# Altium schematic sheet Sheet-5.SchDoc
size 431 x 279 mm; Date: Not shown in title block; ApprovedBy: Not shown in title block; CheckedBy: Not shown in title block; Author: Not shown in title block; CompanyName: Not shown in title block; Engineer: Not shown in title block; Organization: Not shown in title block; Address1: Not shown in title block; Address2: Not shown in title block; Address3: Not shown in title block; Address4: Not shown in title block; DocumentNumber: 3; Revision: Use project parameter SCH_Rev; SheetNumber: 3; SheetTotal: 4; PageSetup: Record=PageOptions|CenterHorizontal=True|CenterVertical=True|PrintScale=1.00|XCorrection=1.00|YCorrection=1.00|PrintKind=0|BorderSize=5000000|LeftOffset=0|BottomOffset=0|Orientation=2|PaperLength=1000|PaperWidth=1000|Scale=100|PaperSource=15|PrintQuality=600|MediaType=1|DitherType=10|PaperKind=Letter|PrintScaleMode=1
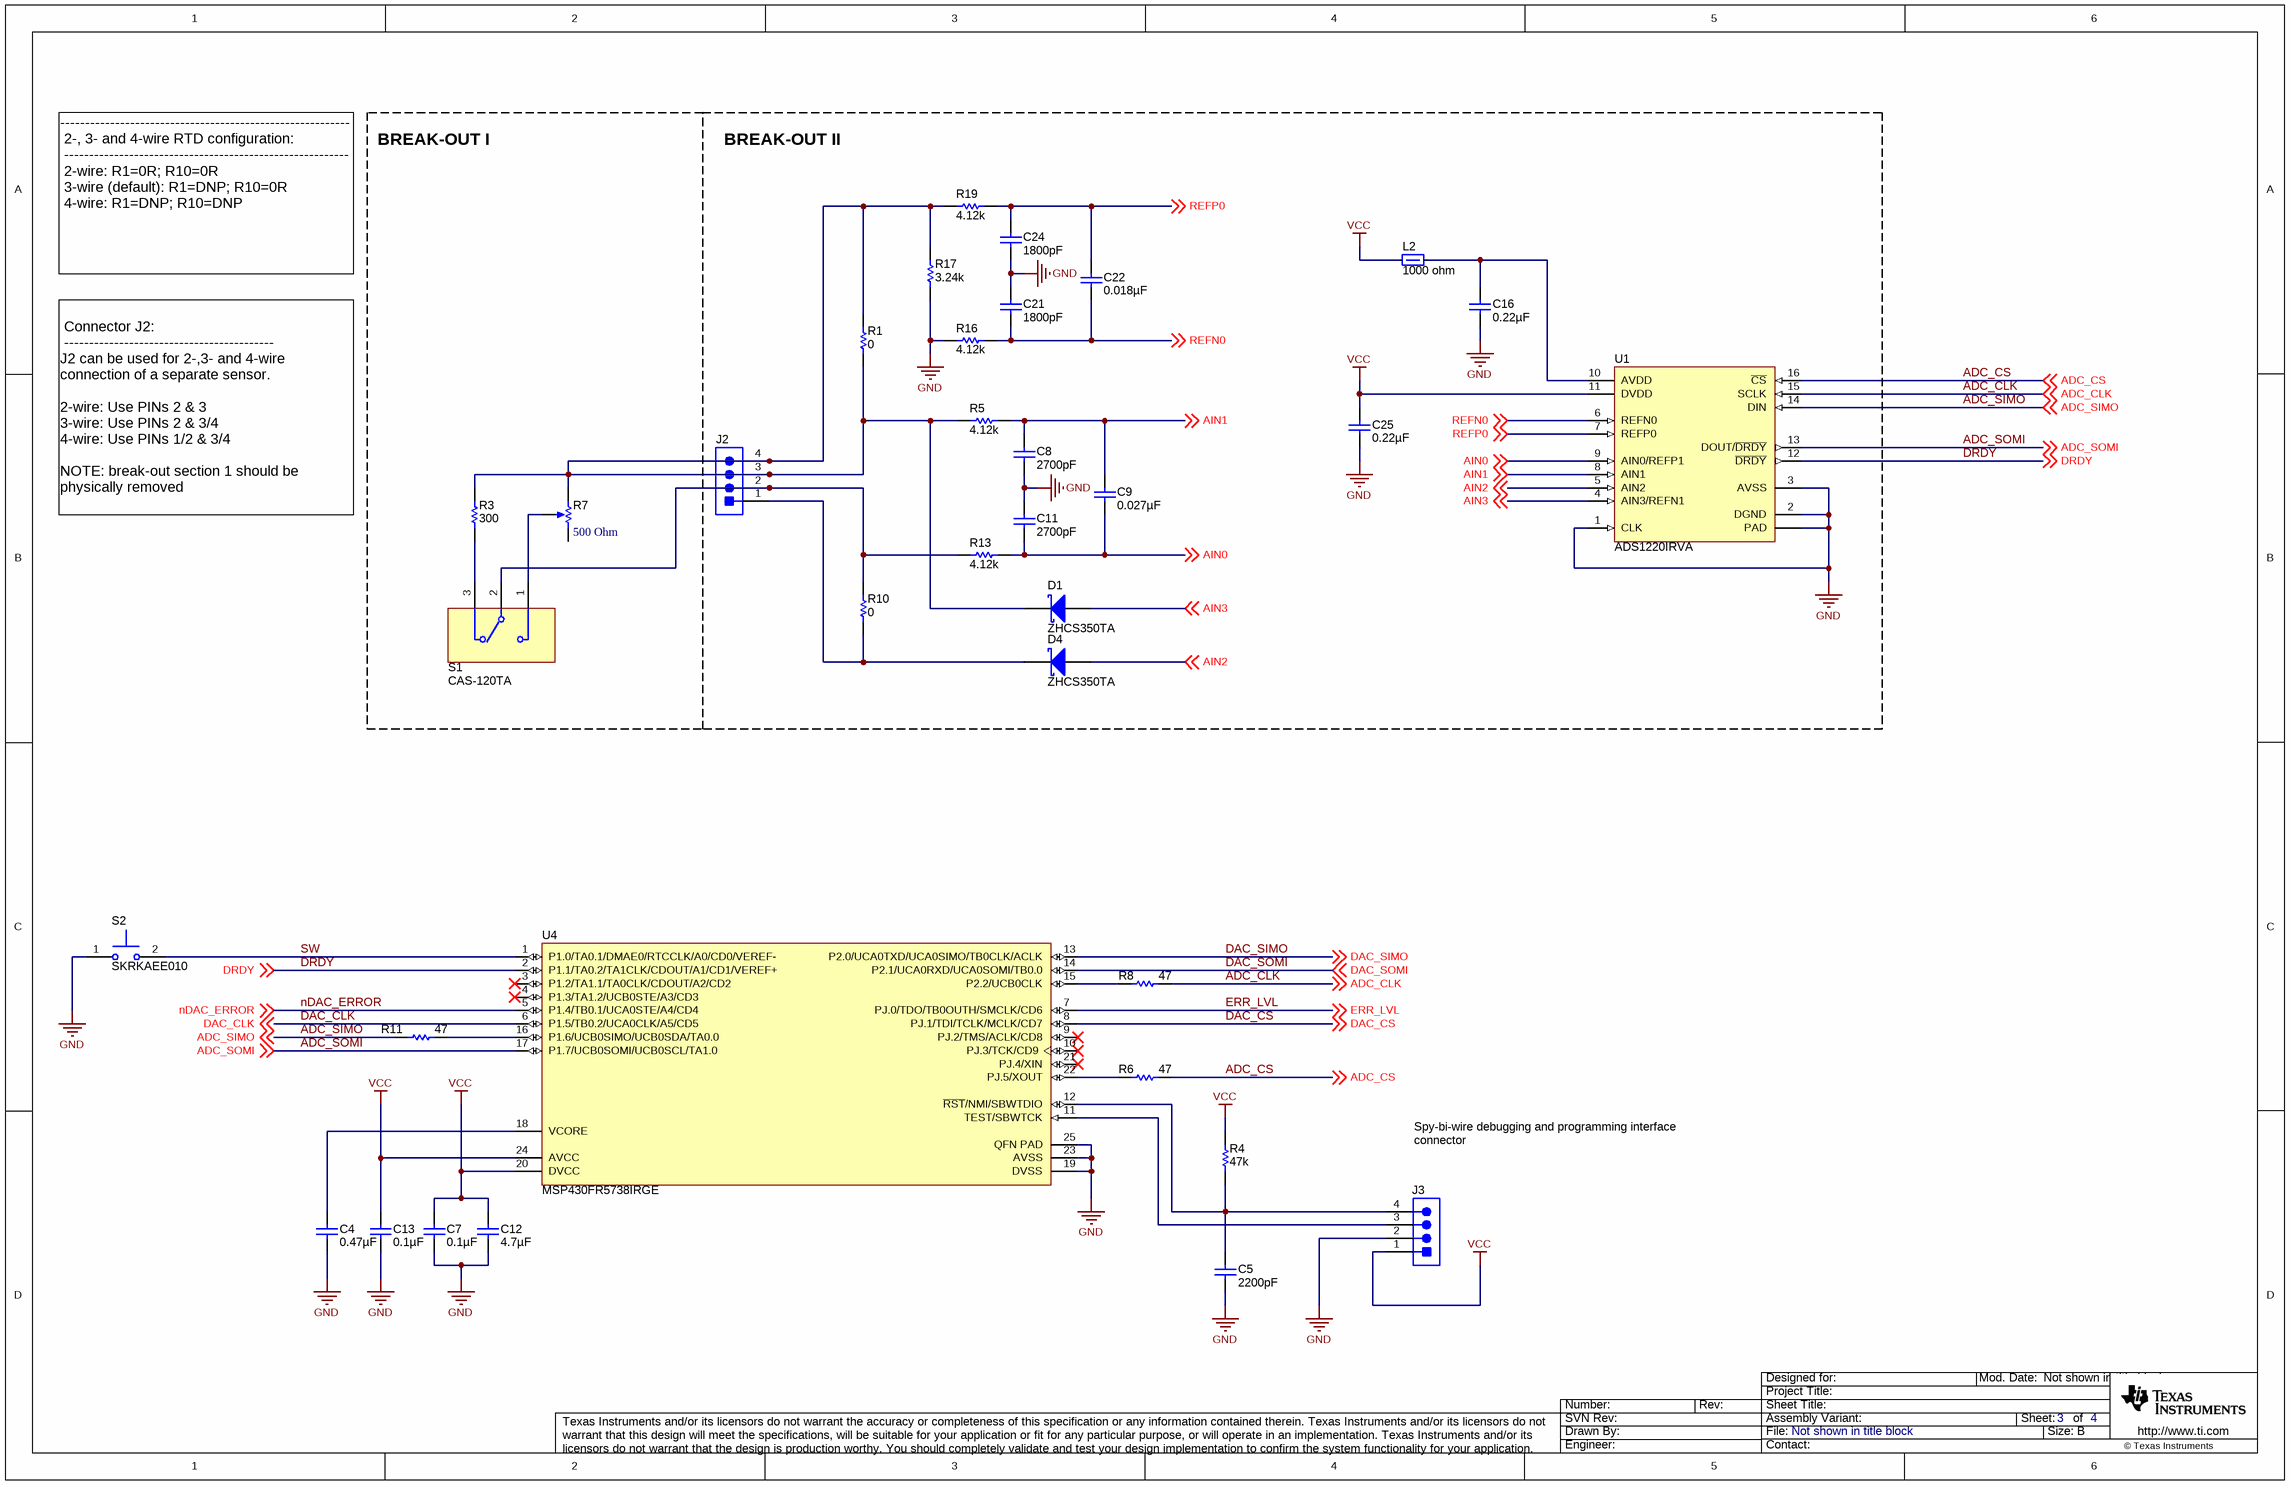
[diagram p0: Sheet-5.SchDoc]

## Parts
C4  ValueDisplayed: 0.47µF  [0402]  (hidden comment: GRM155R60J474KE19D)
C5  ValueDisplayed: 2200pF  [0402]  (hidden comment: GRM155R70J222KA01D)
C7  ValueDisplayed: 0.1µF  [0402]  (hidden comment: C1005X5R0J104K)
C8  ValueDisplayed: 2700pF  [0402S]  (hidden comment: GRM155R72A272KA01D)
C9  ValueDisplayed: 0.027µF  [0603S]  (hidden comment: C0603C273K1RACTU)
C11  ValueDisplayed: 2700pF  [0402S]  (hidden comment: GRM155R72A272KA01D)
C12  ValueDisplayed: 4.7µF  [0402]  (hidden comment: C1005X5R0J475M050BC)
C13  ValueDisplayed: 0.1µF  [0402]  (hidden comment: C1005X5R0J104K)
C16  ValueDisplayed: 0.22µF  [0402]  (hidden comment: GRM155R60J224KE01D)
C21  ValueDisplayed: 1800pF  [0402S]  (hidden comment: GRM155R72A182KA01D)
C22  ValueDisplayed: 0.018µF  [0603S]  (hidden comment: C0603C183K1RACTU)
C24  ValueDisplayed: 1800pF  [0402S]  (hidden comment: GRM155R72A182KA01D)
C25  ValueDisplayed: 0.22µF  [0402]  (hidden comment: GRM155R60J224KE01D)
D1  ZHCS350TA  [SOD-523]
D4  ZHCS350TA  [SOD-523]
J2  850-10-004-20-001000  [Mill-Max_850-10-004-20-001000]  (value not drawn)
J3  850-10-004-40-001000  [Mill-max_850-10-004-40-001000]  (value not drawn)
L2  value 1000 ohm  [0402]  (hidden comment: BLM15HG102SN1D)
R1  value 0  [0402]  (hidden comment: CRCW04020000Z0ED)
R3  value 300  [0603S]  (hidden comment: RG1608P-301-B-T5)
R4  value 47k  [0402]  (hidden comment: CRCW040247K0JNED)
R5  value 4.12k  [0603S]  (hidden comment: RG1608P-4121-B-T5)
R6  value 47  [0402]  (hidden comment: CRCW040247R0JNED)
R7  value 500 Ohm  [Bourns_3223W]  (hidden comment: 3223W-1-501E)
R8  value 47  [0402]  (hidden comment: CRCW040247R0JNED)
R10  value 0  [0402]  (hidden comment: CRCW04020000Z0ED)
R11  value 47  [0402]  (hidden comment: CRCW040247R0JNED)
R13  value 4.12k  [0603S]  (hidden comment: RG1608P-4121-B-T5)
R16  value 4.12k  [0603S]  (hidden comment: RG1608P-4121-B-T5)
R17  value 3.24k  [1206L]  (hidden comment: PFC-W1206R-12-3241-B)
R19  value 4.12k  [0603S]  (hidden comment: RG1608P-4121-B-T5)
S1  CAS-120TA  [SW_CAS-120TA]
S2  SKRKAEE010  [SW_SKRKAEE010]
U1  ADS1220IRVA  [RVA0016A]
U4  MSP430FR5738IRGE  [RGE0024G]

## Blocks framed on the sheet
BREAK-OUT I: R3 R7 S1

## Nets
GND: C4.2 C5.2 C7.2 C8.2 C11.1 C12.2 C13.2 C16.2 C21.1 C24.2 C25.2 J3.2 R16.1 R17.1 S2.1 U1.1(CLK) U1.2(DGND) U1.3(AVSS) U1.17(PAD) U4.19(DVSS) U4.23(AVSS) U4.25(QFN_PAD)
VCC: C7.1 C12.1 C13.1 C25.1 J3.1 L2.1 R4.2 U1.11(DVDD) U4.20(DVCC) U4.24(AVCC)
ADC_CLK: R8.2 U1.15(SCLK) ; off-sheet ADC_CLK
ADC_CS: R6.2 U1.16(~{CS}) ; off-sheet ADC_CS
ADC_SIMO: R11.1 U1.14(DIN) ; off-sheet ADC_SIMO
ADC_SOMI: U1.13(DOUT/~{DRDY}) U4.17(P1.7/UCB0SOMI/UCB0SCL/TA1.0) ; off-sheet ADC_SOMI
AIN0: C9.2 C11.2 R13.2 U1.9(AIN0/REFP1) ; off-sheet AIN0
AIN1: C8.1 C9.1 R5.2 U1.8(AIN1) ; off-sheet AIN1
AIN2: D4.2(A) U1.5(AIN2) ; off-sheet AIN2
AIN3: D1.2(A) U1.4(AIN3/REFN1) ; off-sheet AIN3
DAC_CLK: U4.6(P1.5/TB0.2/UCA0CLK/A5/CD5) ; off-sheet DAC_CLK
DAC_CS: U4.8(PJ.1/TDI/TCLK/MCLK/CD7) ; off-sheet DAC_CS
DAC_SIMO: U4.13(P2.0/UCA0TXD/UCA0SIMO/TB0CLK/ACLK) ; off-sheet DAC_SIMO
DAC_SOMI: U4.14(P2.1/UCA0RXD/UCA0SOMI/TB0.0) ; off-sheet DAC_SOMI
DRDY: U1.12(~{DRDY}) U4.2(P1.1/TA0.2/TA1CLK/CDOUT/A1/CD1/VEREF+) ; off-sheet DRDY
ERR_LVL: U4.7(PJ.0/TDO/TB0OUTH/SMCLK/CD6) ; off-sheet ERR_LVL
nDAC_ERROR: U4.5(P1.4/TB0.1/UCA0STE/A4/CD4) ; off-sheet nDAC_ERROR
REFN0: C21.2 C22.2 R16.2 U1.6(REFN0) ; off-sheet REFN0
REFP0: C22.1 C24.1 R19.2 U1.7(REFP0) ; off-sheet REFP0
SW: S2.2 U4.1(P1.0/TA0.1/DMAE0/RTCCLK/A0/CD0/VEREF-)
NetC4_1: C4.1 U4.18(VCORE)
NetC5_1: C5.1 J3.4 R4.1 U4.12(~{RST}/NMI/SBWTDIO)
NetC16_1: C16.1 L2.2 U1.10(AVDD)
NetD1_1: D1.1(K) J2.3 J2.4 R1.1 R1.2 R3.2 R5.1 R7.1(CCW) R17.2 R19.1
NetD4_1: D4.1(K) J2.1 R10.1
NetJ2_2: J2.2 R10.2 R13.1 S1.2
NetJ3_3: J3.3 U4.11(TEST/SBWTCK)
NetR3_1: R3.1 S1.3
NetR6_1: R6.1 U4.22(PJ.5/XOUT)
NetR7_2: R7.2(WIPER) S1.1
NetR8_1: R8.1 U4.15(P2.2/UCB0CLK)
NetR11_2: R11.2 U4.16(P1.6/UCB0SIMO/UCB0SDA/TA0.0)

Not connected (* = marked no-connect by the designer): R7 3(CW); U4 3(P1.2/TA1.1/TA0CLK/CDOUT/A2/CD2)* 4(P1.3/TA1.2/UCB0STE/A3/CD3)* 9(PJ.2/TMS/ACLK/CD8)* 10(PJ.3/TCK/CD9)* 21(PJ.4/XIN)*

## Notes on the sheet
- BREAK-OUT II
- ----------------------------------------------------------
  2-, 3- and 4-wire RTD configuration:
  ---------------------------------------------------------
  2-wire: R1=0R; R10=0R
  3-wire (default): R1=DNP; R10=0R
  4-wire: R1=DNP; R10=DNP
- Connector J2:
  ------------------------------------------
  J2 can be used for 2-,3- and 4-wire connection of a separate sensor.
  2-wire: Use PINs 2 & 3
  3-wire: Use PINs 2 & 3/4
  4-wire: Use PINs 1/2 & 3/4
  NOTE: break-out section 1 should be physically removed
- (near J3) Spy-bi-wire debugging and programming interface
  connector

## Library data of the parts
C4 = GRM155R60J474KE19D: CAP, CERM, 0.47uF, 6.3V, +/-10%, X5R, 0402; Manufacturer: MuRata; Polarized: N; CompType: Capacitor; U/M: EA; Cap_F: 0.00000047; Tolerance_%: 10; Value1: Unknown; VDC_V: 6.3; TaMin_C: -55; TaMax_C: 85
C5 = GRM155R70J222KA01D: CAP, CERM, 2200pF, 6.3V, +/-10%, X7R, 0402; Manufacturer: MuRata; Polarized: N; CompType: Capacitor; U/M: EA; Cap_F: 0.0000000022; Tolerance_%: 10; Value1: Unknown; VDC_V: 6.3; TaMin_C: -55; TaMax_C: 125
C7 C13 = C1005X5R0J104K: CAP, CERM, 0.1uF, 6.3V, +/-10%, X5R, 0402; Manufacturer: TDK; Polarized: N; CompType: Capacitor; U/M: EA; Cap_F: 0.0000001; Tolerance_%: 10; ESR_Ohm: 0.0186; Value1: 0.0186 ohm; VDC_V: 6.3; TaMin_C: -55; TaMax_C: 85
C8 C11 = GRM155R72A272KA01D: CAP, CERM, 2700pF, 100V, +/-10%, X7R, 0402; Manufacturer: MuRata; Polarized: N; CompType: Capacitor; U/M: EA; Cap_F: 0.0000000027; Tolerance_%: 10; Value1: Unknown; VDC_V: 100; TaMin_C: -55; TaMax_C: 125; Cap_Case: 0402
C9 = C0603C273K1RACTU: CAP, CERM, 0.027uF, 100V, +/-10%, X7R, 0603; Manufacturer: Kemet; Polarized: N; CompType: Capacitor; U/M: EA; Cap_F: 0.000000027; Tolerance_%: 10; Value1: Unknown; VDC_V: 100; TaMin_C: -55; TaMax_C: 125; Cap_Case: 0603
C12 = C1005X5R0J475M050BC: CAP, CERM, 4.7uF, 6.3V, +/-20%, X5R, 0402; Manufacturer: TDK; Polarized: N; CompType: Capacitor; U/M: EA; Cap_F: 0.0000047; Tolerance_%: 20; Value1: Unknown; VDC_V: 6.3; TaMin_C: -55; TaMax_C: 85
C16 C25 = GRM155R60J224KE01D: CAP, CERM, 0.22uF, 6.3V, +/-10%, X5R, 0402; Manufacturer: MuRata; Polarized: N; CompType: Capacitor; U/M: EA; Cap_F: 0.00000022; Tolerance_%: 10; Value1: Unknown; VDC_V: 6.3; TaMin_C: -55; TaMax_C: 85
C21 C24 = GRM155R72A182KA01D: CAP, CERM, 1800pF, 100V, +/-10%, X7R, 0402; Manufacturer: MuRata; Polarized: N; CompType: Capacitor; U/M: EA; Cap_F: 0.0000000018; Tolerance_%: 10; Value1: Unknown; VDC_V: 100; TaMin_C: -55; TaMax_C: 125; Cap_Case: 0402
C22 = C0603C183K1RACTU: CAP, CERM, 0.018uF, 100V, +/-10%, X7R, 0603; Manufacturer: Kemet; Polarized: N; CompType: Capacitor; U/M: EA; Cap_F: 0.000000018; Tolerance_%: 10; Value1: Unknown; VDC_V: 100; TaMin_C: -55; TaMax_C: 125; Cap_Case: 0603
D1 D4 = ZHCS350TA: Diode, Schottky, 40V, 0.35A, SOD-523; Manufacturer: Diodes Inc.; U/M: EA; Vf_V: 0.65; Value2: 0.65V; Io_A: 0.35; Vr_V: 40
J2 = 850-10-004-20-001000: Header, 4x1, 50mil, R/A, TH; Manufacturer: Mill-Max; SymbolCreator: a0412235; U/M: EA
J3 = 850-10-004-40-001000: Header, 4x1, 50mil, R/A, SMT; Manufacturer: Mill-Max; SymbolCreator: a0412235; U/M: EA
L2 = BLM15HG102SN1D: 0.25A Ferrite Bead, 1000 ohm @ 100MHz, SMD; Manufacturer: MuRata; Imax_A: 0.25; Irms: 0.25A @ C rise; Isat: 0.25A @ % inductance drop; DCR_ohm: 1.1; Value1: 1.1 ohm; ZTyp@100MHz_Ohm: 1000; U/M: EA
R1 R10 = CRCW04020000Z0ED: RES, 0 ohm, 5%, 0.063W, 0402; Manufacturer: Vishay-Dale; CompType: Resistor; Value_Code: 0000; Tolerance_%: 5; Power_W: 0.063; VDC_V: 50; TempCo: 200 ppm/C; EIA_Code: E24; U/M: EA
R3 = RG1608P-301-B-T5: RES, 300 ohm, 0.1%, 0.1W, 0603; Manufacturer: Susumu Co Ltd; CompType: Resistor; Value_Code: 300R; Tolerance_%: 0.1; VDC_V: 75; TempCo: 25 ppm/C; U/M: EA
R4 = CRCW040247K0JNED: RES, 47k ohm, 5%, 0.063W, 0402; Manufacturer: Vishay-Dale; CompType: Resistor; Res_ohm: 47000; Value_Code: 47k0; Tolerance_%: 5; Power_W: 0.063; VDC_V: 50; TempCo: 200 ppm/C; EIA_Code: E24; U/M: EA
R5 R13 R16 R19 = RG1608P-4121-B-T5: RES, 4.12k ohm, 0.1%, 0.1W, 0603; Manufacturer: Susumu Co Ltd; CompType: Resistor; Res_ohm: 4120; Value_Code: 4k12; Tolerance_%: 0.1; VDC_V: 75; TempCo: 25 ppm/C; EIA_Code: E192; U/M: EA
R6 R8 R11 = CRCW040247R0JNED: RES, 47 ohm, 5%, 0.063W, 0402; Manufacturer: Vishay-Dale; CompType: Resistor; Value_Code: 47R0; Tolerance_%: 5; Power_W: 0.063; VDC_V: 50; TempCo: 200 ppm/C; EIA_Code: E24; U/M: EA
R7 = 3223W-1-501E: TRIMMER 500 OHM 0.125W SMD; Manufacturer: Bourns; Sim Note: Enter the Resistance value and the set point into parameter fields.; SymbolCreator: a0412235
R17 = PFC-W1206R-12-3241-B: RES, 3.24k ohm, 0.1%, 0.333W, 1206; Manufacturer: TT Electronics/IRC; CompType: Resistor; Res_ohm: 3240; Value_Code: 3k24; Tolerance_%: 0.1; Power_W: 0.333; TempCo: 10 ppm/C; EIA_Code: E192; U/M: EA
S1 = CAS-120TA: Switch, Slide, SPDT  100mA, SMT; Manufacturer: Copal Electronics; SymbolCreator: a0411947; VDC_V: 6; SwitchFunction: On-On; PositionCount: 1; CurrentRating_mA: 100
S2 = SKRKAEE010: Switch, Push Button, SMD; Manufacturer: Alps; SymbolCreator: a0412235; Circuit: SPST-NO; VDC_V: 12; SwitchFunction: Off-Mom; PositionCount: 1; CurrentRating_mA: 50
U1 = ADS1220IRVA: Low-Power, Low-Noise, 24-Bit Analog-to-Digital Converter for Small Signal Sensors, RVA0016A; Alternate Manufacturer: None; Manufacturer: Texas Instruments; SymbolCreator: x0208326; CompType: IC; U/M: EA
U4 = MSP430FR5738IRGE: 24 MHz Mixed Signal Microcontroller, 1024 B SRAM and 17 GPIOs, -40 to 85 degC, RGE0024G; Manufacturer: Texas Instruments; Alternate Manufacturer: None; ADC: 10-bit SAR; ADC Channels: 10; Brown Out Reset: Yes; DMA: 3; Eco-Plan: Green (RoHS & no Sb/Br); FRAM(KB): 16; Frequency(MHz): 24; GPIO: 17; Multiplier: 32x32; SRAM(B): 1024; SubFamily: FRAM Series; USCI_A (UART/LIN/IrDA/SPI): 1; SymbolCreator: Altium; CompType: IC; U/M: EA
